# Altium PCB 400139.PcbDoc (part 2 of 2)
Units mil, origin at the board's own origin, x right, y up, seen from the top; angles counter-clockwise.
Board outline 2800 x 2160 mil, 2 copper layers (Top Layer, Bottom Layer), stack 61.8 mil thick; 154 components, 167 nets, 587 pads, 544 vias.
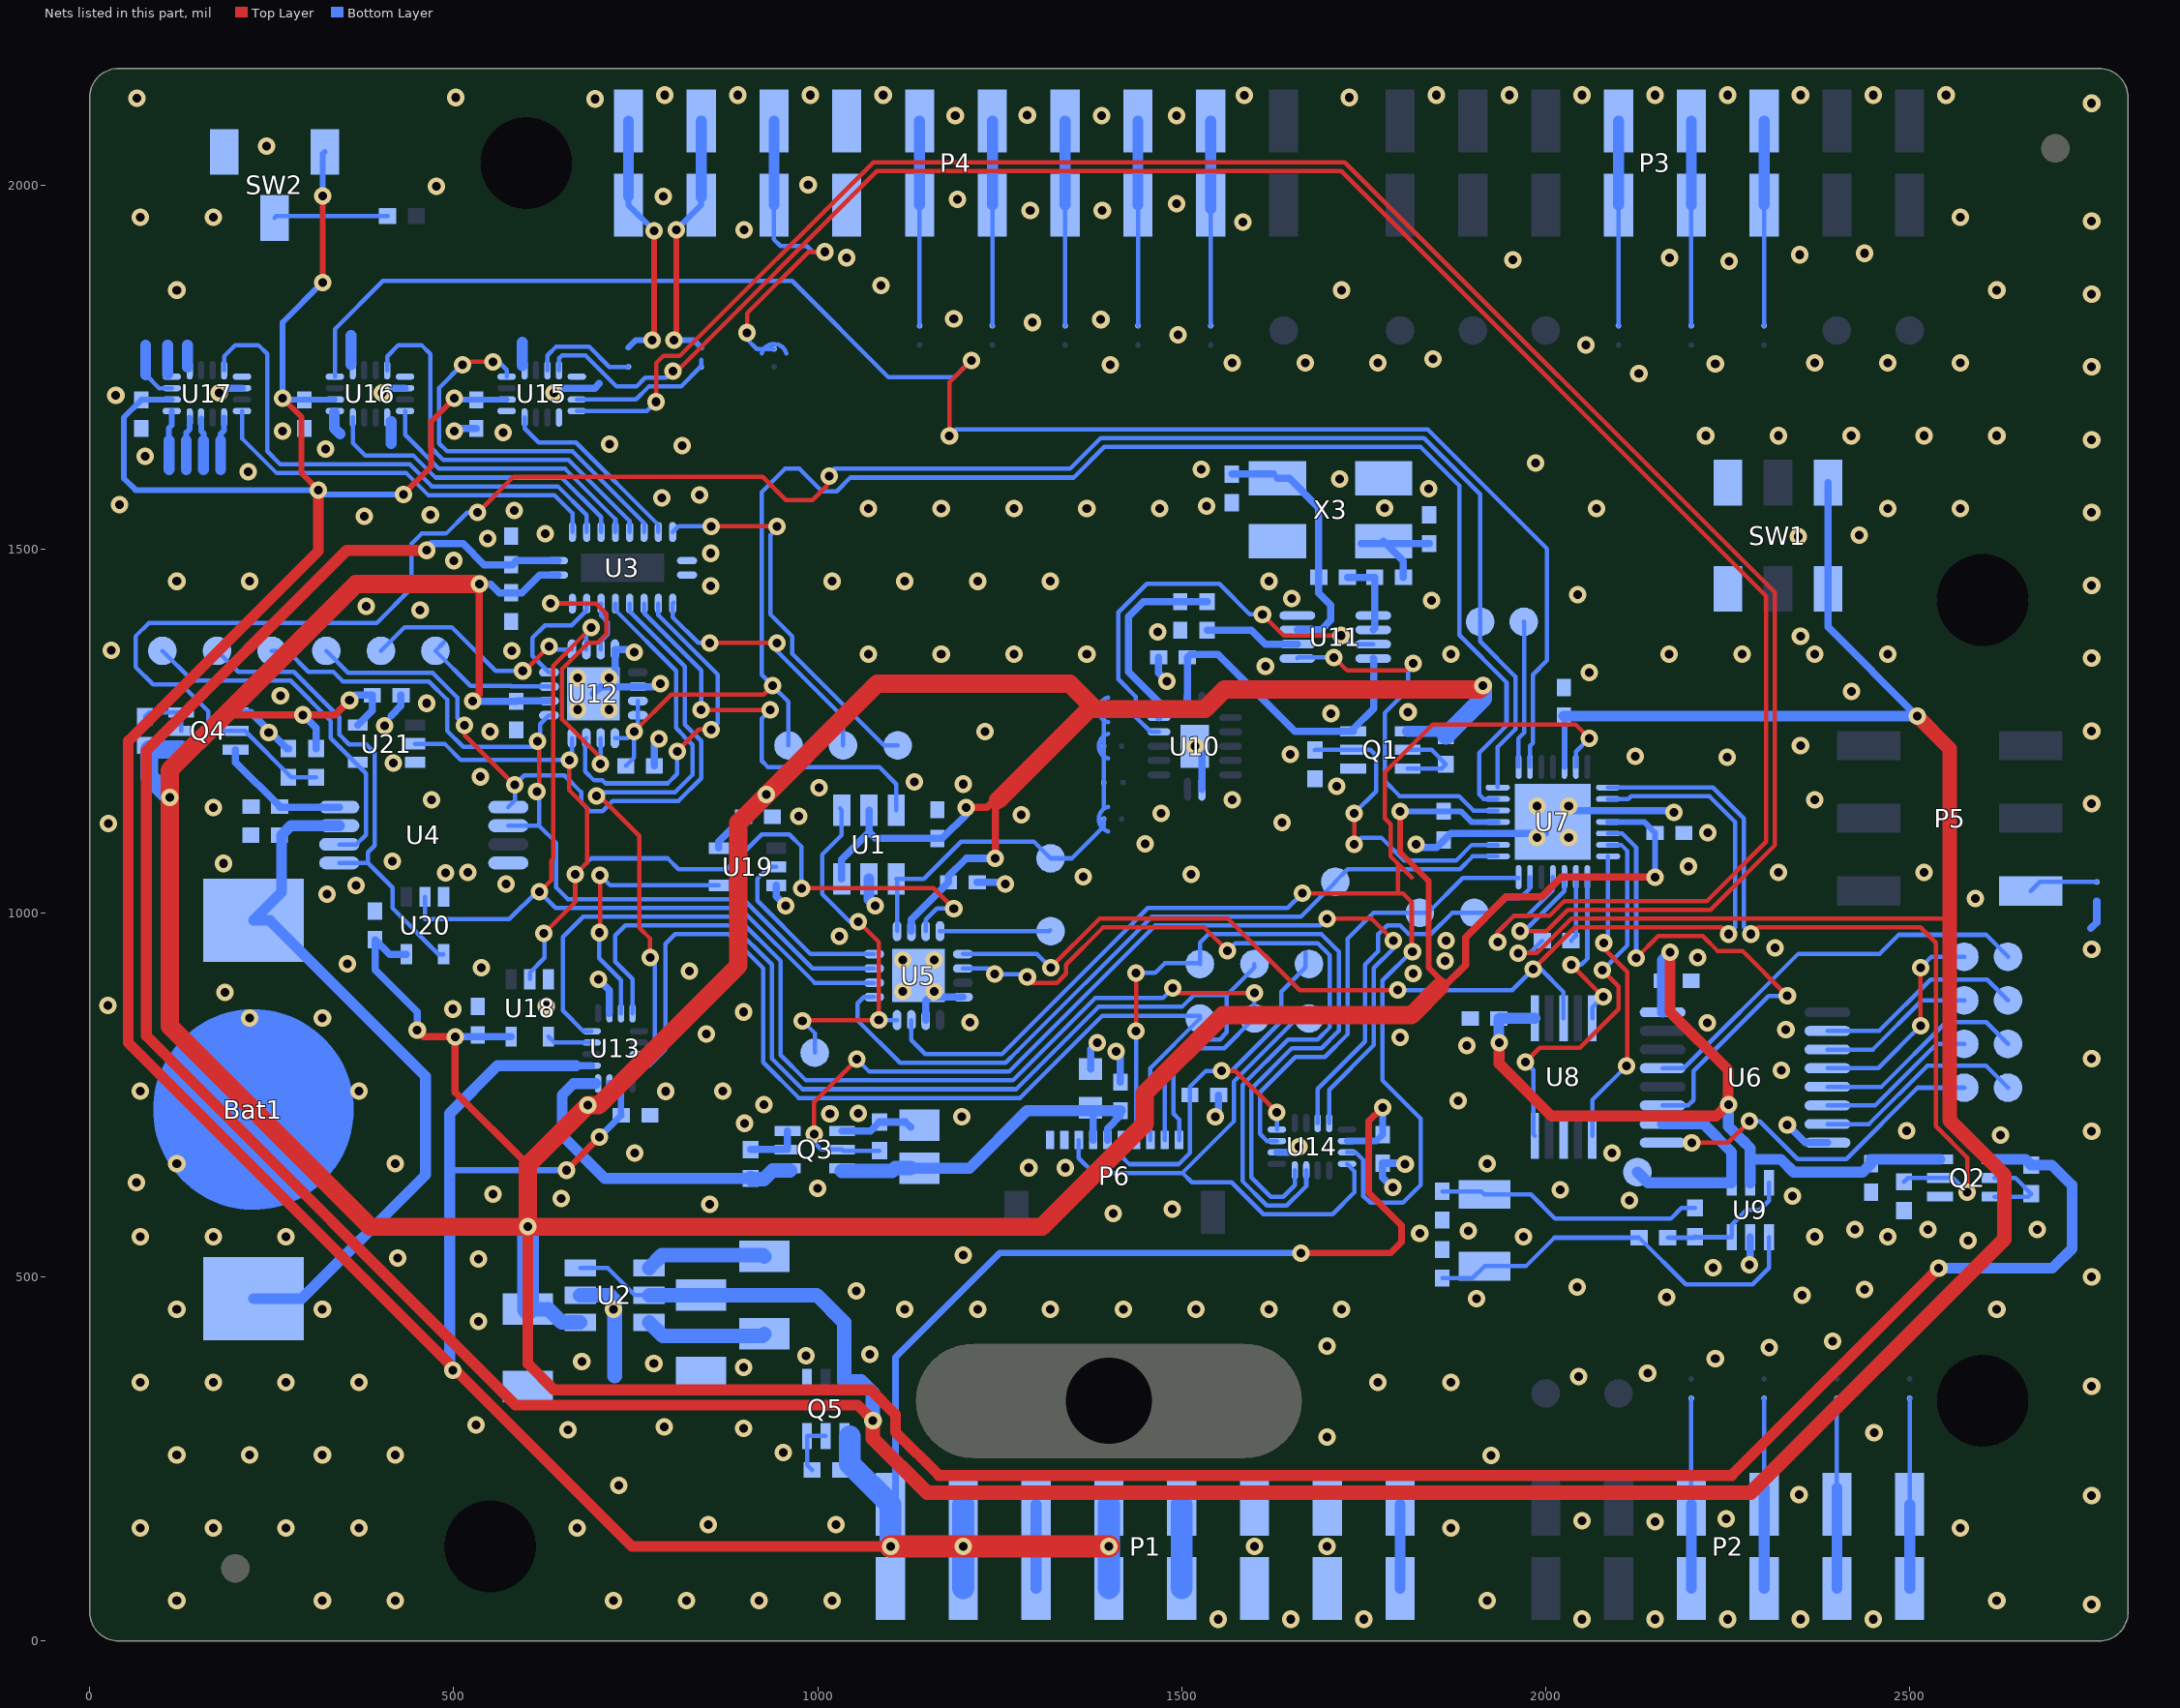
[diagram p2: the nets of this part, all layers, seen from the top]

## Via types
v1: diameter 24, hole 12, Top Layer to Bottom Layer, tented both sides, 544 vias

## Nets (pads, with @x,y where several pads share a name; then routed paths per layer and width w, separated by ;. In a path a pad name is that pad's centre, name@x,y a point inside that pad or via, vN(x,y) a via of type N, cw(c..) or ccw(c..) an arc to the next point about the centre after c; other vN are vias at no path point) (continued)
GND: Bat1.2 C1.1 C2.1 C4.1 C5.1 C6.1 C7.1 C8.1 C9.1 C10.1 C11.1 C12.1 C13.1 C14.1 C15.1 C16.1 C17.1 C18.1 C19.1 C20.2 C21.2 C22.1 C23.1 C24.2 C25.2 C26.1 C27.2 C28.1 C29.1 C30.1 C31.1 C32.1 C33.2 C34.2 C35.2 P1.6 P1.7 P4.7 P6.9 P6.10 Q1.1 Q2.1 Q3.1 Q4.1 Q5.1 R2.2 R4.2 R7.2 R8.1 R13.1 R14.2 SB13.1 SW1.3 SW1.6 SW2.3 U1.2 U2.2 U3.10 U3.11 U4.4 U5.4 U5.6 U5.17 U6.8 U7.3 U7.17 U7.29 U8.3 U9.2 U10.7 U10.15 U11.4 U12.4 U12.6 U12.17 U13.6 U14.6 U15.6 U16.6 U17.6 U18.3 U19.3 U20.3 U21.3 X3.2 X3.4 | length 1783.5
  Bottom Layer w10: v1(178,1714) 184.87,1720.87 U17.6@209.23,1720.87 ; Q4.1@200.4,1275.59 221.41,1275.59 271.31,1225.69 R14.2@273,1225.69 ; v1(402,1714) 408.87,1720.87 U16.6@433.23,1720.87 ; 414,1271 427.69,1284.69 C35.2@427.69,1299 ; v1(501,1662) 504.31,1665.32 C30.1@531,1665.32 ; v1(638,1714) 644.87,1720.87 U15.6@669.23,1720.87 693.87,1720.87 700,1727 ; U12.17@692,1301 701.84,1310.84 U12.6@753.02,1310.84 779.84,1310.84 v1(784,1315) ; v1(699,909) 714.13,893.87 U13.6@714.13,862.23 ; U12.17@721.53,1327 U12.4@721.53,1362.02 743.98,1362.02 v1(748,1358) ; R13.1@775.69,1202 775.69,1232.68 v1(782,1239) ; U19.3@943,1037.82 943,1023 v1(956,1010) ; Q3.1@1033.52,700.59 1072.65,700.59 R7.2@1084.87,712.81 1120.76,712.81 C16.1@1127.87,705.7 ; U5.6@1148.37,852.95 1148.37,879.37 1159,890 1164.55,884.45 U5.4@1199.55,884.45 ; C7.1@1219.21,1041.98 1256.02,1041.98 v1(1258,1040) ; C19.1@1374.87,785.67 1374.87,812.87 v1(1384,822) ; v1(1410,810) 1415.87,804.13 C18.1@1415.87,767.78 ; C22.1@1468.31,1351 1468.31,1329.68 v1(1480,1318) ; v1(1518,1229) 1527.84,1219.16 U10.7@1527.84,1169.94 ; v1(1546,720) 1550.69,724.68 C17.1@1550.69,750 ; U14.6@1630.77,671.13 1631.19,671.54 1653.54,671.54 v1(1661,679) ; v1(1790,623) 1776,637 C28.1@1776,656.31 1805.69,656.31 v1(1807,655) ; v1@1820,1090 1850,1090 1869.25,1109.25 U7.3@1934.21,1109.25 1999.25,1109.25 U7.29@2000,1110 ; U7.29@2030,1140 2030.75,1140.75 U7.17@2085.79,1140.75 2169.25,1140.75 v1@2170,1140 ; v1(2280,517.06) 2281,518.06 U9.2@2281,554.66 ; v1(2332,709) 2356.52,684.48 U6.8@2387.13,684.48 ; 2749,979 2757,987 SB13.1@2757,1016
  Bottom Layer w15: v1@1070.53,1018.47 U1.2@1070.53,1046.73
  Bottom Layer w20: U2.2@673.91,475 714.16,475 721.16,468 721.16,364.16
  other v1: 1550,30 1650,30 1750,30 2050,30 2150,30 2250,30 2350,30 2450,30 2750,50 119.75,55.47 319.75,55.47 419.75,55.47 719.75,55.47 819.75,55.47 919.75,55.47 1019.75,55.47 1919.75,55.47 2619.75,55.47 1600,130 1700,130 69.75,155.47 169.75,155.47 269.75,155.47 369.75,155.47 669.75,155.47 1869.75,155.47 2569.75,155.47 850,160 1025,160 2150,164 2050,165 2248,168 2750,200 2348,201 727,214 119.75,255.47 219.75,255.47 319.75,255.47 419.75,255.47 1925,255 953,259 1700,280 2451,286 657,290 898,292 789,294 531,297 2750,350 69.75,355.47 169.75,355.47 269.75,355.47 369.75,355.47 1769.75,355.47 1869.75,355.47 2045,363 2140,368 898,376 775,381 676,384 2233,388 984,392 1072,394 2307,403 1700,405 2394,412 534,439 119.75,455.47 319.75,455.47 719.75,455.47 1119.75,455.47 1219.75,455.47 1319.75,455.47 1419.75,455.47 1519.75,455.47 1619.75,455.47 1719.75,455.47 2619.75,455.47 1905,470 2166,472 2352,475 1053,481 2438,483 2043,486 2750,500 2230,513.06 534,525 423,526 1200,530 2580,550 69.75,555.47 169.75,555.47 269.75,555.47 1969.75,555.47 2369.75,555.47 2469.75,555.47 1827,560 1894,563.06 2425,565 2525,565 2675,565 1406,587 1487,593 852,600 2115,605 648,608 2339,611 554,614 2020,620 1000,622 64,630 1290,650 1340,650 119.75,655.47 419.75,655.47 1919.75,655.47 749,670 2091,670 2625,695 2750,700 2496,701 899.87,711.13 1198,720 1016.87,724.13 1056,725 926,737 1880,742 69.75,755.47 369.75,755.47 791,755 869.75,755.47 2323.95,784.05 2750,800 1892,818 1800,829 847,834 2330,840 2221.95,849.05 1209,850 219.75,855.47 319.75,855.47 898,864 499,868 627,872 25,873 186,891 1116.87,892.32 1160.18,892.32 1818,917 824,920 538,925 354,930 1862,934 1116.87,935.63 1160.18,935.63 2208.95,939.05 2750,950 2315,952 1863,962 1030,968 1079,1010 2590,1020 326,1026 366,1038 572,1040 1365,1050 1513,1053 489,1055 519.75,1055.47 2319.75,1055.47 2519.75,1055.47 2196,1064 184,1068 416,1071 1822,1094 1450,1095 1988.35,1103.35 2031.65,1103.35 2223,1110 26,1123 1638,1124 974,1133 1280,1135 1472,1137 2176,1138 170,1145 1988.35,1146.65 2031.65,1146.65 2750,1150 469.75,1155.47 1569.75,1155.47 2369.75,1155.47 1002,1172 1713,1174 1200,1177 1133,1180 537,1187 417,1206 2249,1214 2123,1215 1649,1218 2350,1230 246,1248 550,1249 1230,1249 2750,1250 405,1257 1705,1274 1811,1276 670.35,1279.35 713.65,1279.35 463,1288 262,1298 2420,1304 670.35,1322.65 713.65,1322.65 2060,1330 1615,1339 2750,1350 1069.75,1355.47 1169.75,1355.47 1269.75,1355.47 1369.75,1355.47 1869.75,1355.47 2169.75,1355.47 2269.75,1355.47 2369.75,1355.47 2469.75,1355.47 580,1360 30,1361 2350,1380 1467,1386 454,1416 380,1421 1843,1429 1651,1432 2044,1437 853,1449 2750,1450 119.75,1455.47 219.75,1455.47 1019.75,1455.47 1119.75,1455.47 1219.75,1455.47 1319.75,1455.47 1619.75,1455.47 500,1484 853,1494 547,1514 2347,1517 2431,1519 626,1521 377,1545 468,1547 2750,1550 583,1553 1069.75,1555.47 1169.75,1555.47 1269.75,1555.47 1369.75,1555.47 1469.75,1555.47 2069.75,1555.47 2469.75,1555.47 2569.75,1555.47 1779,1556 1534,1559 41,1561 786,1570 838,1574 1839,1583 1717,1596 218,1606 1527,1609 1986,1618 76,1627 324,1637 814,1642 714,1644 2750,1650 2219.75,1655.47 2319.75,1655.47 2419.75,1655.47 2519.75,1655.47 2619.75,1655.47 568,1660 265,1662 36,1711 2128,1741 2750,1750 1402,1753 2233,1754 1569.75,1755.47 1669.75,1755.47 1769.75,1755.47 2369.75,1755.47 2469.75,1755.47 2569.75,1755.47 1845,1761 2055,1780 1495,1794 1295,1811 1389,1815 1187,1816 2750,1850 119.75,1855.47 1719.75,1855.47 2619.75,1855.47 1087,1862 2252,1895 1955,1897 1040,1900 2170,1900 2349,1904 2438,1906 899,1938 1584,1949 2750,1950 69.75,1955.47 169.75,1955.47 2569.75,1955.47 1292,1965 1391,1965 1493,1974 1192,1980 788,1984 476,1998 987,2000 243,2053 1189,2095 1390,2095 1493,2095 1288,2096 2750,2112 694,2118 65,2119 503,2120 1730,2120 790,2123.31 890,2123.31 990,2123.31 1090,2123.31 1586,2123 1850,2123.31 1950,2123.31 2050,2123.31 2150,2123.31 2250,2123.31 2350,2123.31 2450,2123.31 2550,2123.31
HF_CLK_CTRL: TP30.1 U1.4 U5.8 | length 524.5
  Top Layer w6: v1(979,852) 979,853 v1(1084,853) 1084,960 v1(1056,988)
  Bottom Layer w6: v1(979,852) 996,835 TP30.1@996,808 ; U1.4@1030.53,1143.82 U1.4@1033.13,1141.22 1033.13,1107.13 1006,1080 1006,1026 1044,988 v1(1056,988) ; v1(1084,853) 1084.05,852.95 U5.8@1109,852.95
HF_OSC_CTRL: U3.7 U15.16 | length 536.8
  Top Layer w6: v1(512,1753) 516,1757 v1(554,1757)
  Bottom Layer w6: v1(512,1753) 480,1721 480,1645 491,1634 663.03,1634 761.53,1535.5 U3.7@761.53,1523.21 ; v1(554,1757) 561.77,1757 572.77,1746 U15.16@572.77,1736.62
HF_OSC_CTRL_3V3: U1.6 U3.14 | length 582.5
  Top Layer w6: v1(840,1279) v1(935,1279)
  Bottom Layer w6: U3.14@761.53,1424.79 761.53,1411.47 840,1333 v1(840,1279) ; v1(935,1279) 923,1267 923,1209 931.5,1200.5 1084.5,1200.5 1107.93,1177.07 U1.6@1107.93,1141.22 U1.6@1108.19,1141.22
HF_OSC_OUT: SB9.1 SB10.1 SB11.1 SB12.1 TP18.1 U1.1 U5.13 | length 549.2
  Bottom Layer w6: U5.13@1109,975 1109,1045.66 U1.1@1107.93,1046.73 1145.73,1046.73 1197,1098 1297,1098 TP18.1@1320,1075 1349,1075 1390.94,1116.94 1393,1119 SB12.1@1393,1129 ; 1393,1142.9 SB11.1@1393,1179 SB10.1@1393,1229 1393,1273 1395,1275
HF_OSC_OUT_SENSE: U3.8 U15.12 | length 263.3
  Bottom Layer w6: U15.12@597.38,1680.52 597.38,1665.62 617,1646 668,1646 781.21,1532.79 U3.8@781.21,1523.21
HF_OSC_OUT_SENSE_3V3: U3.13 U12.11 | length 485.4
  Top Layer w6: v1(807,1222) 837,1252 v1(854,1252)
  Bottom Layer w6: U12.11@682.16,1239.98 680.84,1238.66 680.84,1194.16 693,1182 704.7,1182 708.7,1178 794,1178 807,1191 v1(807,1222) ; U3.13@781.21,1424.79 781.21,1408.76 863,1326.97 863,1261 v1(854,1252)
HF_OSC_PWR_CTRL_3V3: Q1.2 R2.1 U7.2 | length 444.4
  Top Layer w6: v1(1737,1094) v1(1737,1137)
  Bottom Layer w6: R2.1@1683,1223.68 1683.31,1224 Q1.2@1735.6,1224 1759,1224 1767,1216 1767,1167 v1(1737,1137) ; v1(1737,1094) 1746,1103 1774.7,1103 1805.56,1072.13 1877.13,1072.13 1898.5,1093.5 U7.2@1934.21,1093.5
HF_OSC_S\T\_3V3: U7.5 U11.1 | length 521.4
  Top Layer w6: v1(1709,1351) 1727,1333 1808,1333 v1(1818,1343)
  Bottom Layer w6: U11.1@1658.83,1349.47 1660.36,1351 v1(1709,1351) ; v1(1818,1343) 1811,1336 1811,1307 1779,1275 1779,1181 1799.31,1160.69 1880.7,1160.69 1900.64,1140.75 U7.5@1934.21,1140.75
INT: U7.9 U16.16 | length 2349.1
  Top Layer w6: v1(1181,1655) 1181,1729 v1(1211,1759)
  Bottom Layer w6: U16.16@336.77,1736.62 336.77,1801.77 403,1868 965.03,1868 1097.03,1736 1188,1736 v1(1211,1759) ; v1(1181,1655) 1190,1664 1838,1664 2002.01,1499.99 2002.01,1346.99 1982.25,1327.22 1982.25,1233.25 1978.5,1229.5 U7.9@1978.5,1200.79
LCD_CS: U3.5 U16.8 | length 387.2
  Bottom Layer w6: U16.8@433.23,1689.38 433.23,1656.77 480,1610 653.09,1610 722.16,1540.93 U3.5@722.16,1523.21
LCD_CS_3V3: U3.16 U13.11 | length 826.7
  Top Layer w6: v1(696,1161) 699.7,1161 755,1105.7 755,979.7 770,964.7 v1(770,939)
  Bottom Layer w6: v1@696,1166 804.09,1166 828,1189.91 828,1230.7 817.17,1241.53 817.17,1242.17 805.45,1253.89 805.45,1332.55 722.16,1415.84 U3.16@722.16,1424.79 ; U13.11@754.48,806.13 766.05,806.13 776.28,816.35 776.28,932.72 v1(770,939)
LCD_DISP_3V3: TP38.1 U7.28 U14.7 | length 638.5
  Bottom Layer w6: U14.7@1630.77,686.87 1617.13,686.87 1607.5,696.5 1607.5,753.58 1656.23,802.31 1696.82,802.31 1727.69,833.18 1727.69,964.38 1763.3,1000 TP38.1@1827,1000 1838,1000 1886.13,1048.13 U7.28@1962.76,1048.13
LCD_EXTCOMIN_3V3: U5.2 U14.3 | length 1093.7
  Top Layer w6: v1(1288,912) 1296,904 1328.7,904 1341,916.3 1341,929.03 1391.97,980 1531,980 v1(1563,948)
  Bottom Layer w6: U5.2@1199.55,923.82 1235.18,923.82 v1(1243,916) 1284,916 v1(1288,912) ; v1(1563,948) 1573.69,958.69 1686.88,958.69 1703.69,941.88 1703.69,843.12 1686.88,826.31 1646.29,826.31 1583.5,763.53 1583.5,631.84 1617.1,598.23 1644.44,598.23 1671.13,624.91 U14.3@1671.13,646.52
LCD_EXTMODE_3V3: U5.7 U7.13 U14.15 | length 1976.6
  Top Layer w6: v1(1666,1027) 1797,1027 ; 1797,1066 1797,1027 ; v1@1816,947 1816,1015 1804,1027 1797,1027 ; 1816,1048.75 1787,1077.75 1787,1122 1779.31,1129.69 1779.31,1193.34 1844.97,1259 2041,1259 v1(2060,1240)
  Bottom Layer w6: U5.7@1128.69,852.95 1128.69,825.31 1148,806 1253.03,806 1422.03,975 1453.71,1006.69 1645.69,1006.69 v1(1666,1027) ; U14.15@1727.23,671.13 1738.87,671.13 1749.02,660.98 1749.02,611.02 1749.98,611.02 1759,602 1804,602 1828,626 1828,718 1776,770 1776,907 v1@1816,947 ; U7.13@2041.5,1200.79 2041.5,1221.5 v1(2060,1240)
  other v1: 1817,947
LCD_PWR_CTRL: Q3.2 R7.1 U14.12 | length 1363.7
  Top Layer w6: v1(995,696) 995,740 v1(1054,799) ; v1(1700,992) 1761,992 v1(1791,962)
  Bottom Layer w6: v1(995,696) 995,685 1005,675 Q3.2@1033.53,675 1035.08,673.44 R7.1@1084.87,673.44 ; v1(1054,799) 1071,782 1262.97,782 1463.66,982.69 1690.69,982.69 v1(1700,992) ; U14.12@1702.62,711.48 1702.62,757.2 1764,818.58 1764,924.33 1791,951.33 v1(1791,962)
LCD_PWR_CTRL_3V3: TP37.1 U7.27 U14.11 | length 553.6
  Bottom Layer w6: U14.11@1686.87,711.48 1686.87,758.43 1752,823.55 1752,929.3 1770,947.3 1770,970.7 1782.3,983 1800,983 1812,971 1842.3,971 1871.3,1000 TP37.1@1902,1000 1926,1000 1946,1020 1964.63,1020 1978.5,1033.87 U7.27@1978.5,1049.21
LCD_SI_LOCAL: U13.7 U19.4 | length 371.7
  Top Layer w6: v1(700,973) 701,974 v1(701,1052)
  Bottom Layer w6: v1(700,973) 700,937.7 729.87,907.82 U13.7@729.87,862.23 ; v1(701,1052) 715.18,1037.82 U19.4@864.26,1037.82
LCD_SPI_DATA_CTRL_3V3: TP8.1 U5.9 U7.1 | length 1071.1
  Bottom Layer w6: U5.9@1077.5,884.45 1063.45,884.45 1054.87,875.87 1054.87,852.44 1113.3,794 1258,794 1274.5,810.5 1458.69,994.69 1663.38,994.69 1711,1042.3 TP8.1@1711,1043 1728.13,1060.13 1882.1,1060.13 1899.73,1077.76 U7.1@1934.21,1077.76
LF_CNT_3V3: U5.1 U7.16 U8.8 | length 1605.8
  Top Layer w6: v1(1320,925) 1387,992 1564,992 1662,894 v1(1797,894) ; v1(1983,923) 2040.31,980.31 2241.69,980.31 v1(2251,971)
  Bottom Layer w6: U5.1@1199.55,943.5 1301.5,943.5 v1(1320,925) ; v1(1797,894) 1954,894 v1(1983,923) 1993,923 2024.57,891.43 U8.8@2024.57,855.47 ; U7.16@2085.79,1156.5 2113.5,1156.5 2117.24,1160.24 2224.76,1160.24 2260,1125 2260,980 v1(2251,971)
LF_CNTR_CLR_3V3: U6.11 U7.19 | length 709.7
  Top Layer w6: v1(2124.36,938) 2154.68,968.31 2215.69,968.31 2236,948 2270,948 v1(2332,886)
  Bottom Layer w6: U7.19@2085.79,1109.25 2105.08,1109.25 2124.36,1089.97 v1(2124.36,938) ; U6.11@2160.76,735.66 2195.56,735.66 2203,743.1 2203,783.03 2305.97,886 v1(2332,886)
LF_OSC_OUT: TP19.1 U6.10 U9.4 | length 288.2
  Bottom Layer w15: TP19.1@2126,644.06 2140.6,629.46 U9.4@2255.41,629.46 2255.41,671.66 2217,710.07 U6.10@2160.76,710.07
LF_OSC_PWR_CTRL_3V3: Q2.2 R4.1 U7.15 | length 1091.4
  Top Layer w6: v1(2282,971) 2291.31,980.31 2514.69,980.31 2536,959 2536,707.13 2579,664.13 v1(2579,616.31)
  Bottom Layer w6: U7.15@2085.79,1172.24 2229.73,1172.24 2272,1129.97 2272,981 v1(2282,971) ; R4.1@2492,630.68 2497.32,636 Q2.2@2541.6,636 2559.31,636 v1(2579,616.31)
LF_SEL0_3V3: U7.21 U8.1 | length 419.3
  Top Layer w6: v1(2080,959) 2080,951 2112,919 2112,791 v1(2111,790)
  Bottom Layer w6: U8.1@2063.95,694.05 2063.95,742.95 v1(2111,790) ; v1(2080,959) 2085.79,964.79 U7.21@2085.79,1077.76
LF_SEL1_3V3: U7.22 U8.10 | length 235.6
  Top Layer w6: v1(2035,929) v1(2079,885)
  Bottom Layer w6: v1(2035,929) 2049,929 2057.24,937.24 U7.22@2057.24,1049.21 ; U8.10@2063.94,855.47 2063.94,869.94 v1(2079,885)
LF_SEL_EN_3V3: U7.20 U8.5 | length 535.1
  Top Layer w6: v1(1972,795) 1992,815 2047,815 2100,868 2100,899.34 v1(2078,921.34)
  Bottom Layer w6: v1(1972,795) 1982.95,784.05 1982.95,696.31 U8.5@1985.2,694.05 ; v1(2078,921.34) 2112.36,955.7 2112.36,1085 2103.86,1093.5 U7.20@2085.79,1093.5
MISO: U3.3 U17.4 | length 721.9
  Bottom Layer w6: U17.4@184.62,1745.48 184.62,1764.62 200,1780 231.7,1780 244,1767.7 244,1634 262,1616 440,1616 470,1586 643.15,1586 682.79,1546.36 U3.3@682.79,1523.21
MISO_3V3: U3.18 U12.16 | length 155.9
  Bottom Layer w6: U12.16@630.98,1330.53 608.34,1353.17 608.34,1378 625.34,1395 662,1395 682.79,1415.79 U3.18@682.79,1424.79
MISO_LOCAL: TP27.1 U4.2 U5.11 U12.13 | length 1212.1
  Top Layer w6: v1(615,1236) 617.2,1233.8 v1@617.2,1166.8
  Bottom Layer w6: TP27.1@250,1360 272,1360 300.69,1331.31 334.69,1331.31 348,1318 466.03,1318 491,1293.03 491,1250 513,1228 v1@613,1228 ; U4.2@575.14,1119.8 617,1119.8 617.2,1120 ; v1@617.2,1166.8 617.2,1120 ; v1@618.75,1243.75 618.75,1259.25 U12.13@630.98,1271.47 ; U5.11@1077.5,923.82 993.15,923.82 897.97,1019 657,1019 641,1035 641,1096.2 617.2,1120
  other v1: 614.2,1166.8
MLCD_DISP: C17.2 P6.5 TP24.1 U14.8 | length 611.9
  Top Layer w6: v1(1555,783) 1574,783 v1(1630.77,726.23)
  Bottom Layer w6: P6.5@1417.72,688.09 1417.72,665.28 1428,655 1496,655 1511.36,670.36 C17.2@1511.31,750 C17.2@1511.31,750 1511.31,761.31 1533,783 v1(1555,783) 1568.57,783 1637,851.43 1637,892 1670,925 TP24.1@1670,945.7 ; U14.8@1630.77,702.62 v1(1630.77,726.23)
MLCD_EXTCOMIN: P6.4 TP23.1 U14.4 | length 1038.9
  Top Layer w6: v1(1437.4,838) v1(1437.4,917.6)
  Bottom Layer w6: P6.4@1437.4,688.09 v1(1437.4,838) ; v1(1437.4,917.6) 1463.6,917.6 1477,931 1524,931 TP23.1@1525,930 1525,959 1536.69,970.69 1691.85,970.69 1715.69,946.85 1715.69,838.15 1691.85,814.31 1651.26,814.31 1595.5,758.55 1595.5,636.81 1622.07,610.23 1639.47,610.23 1655.38,626.14 U14.4@1655.38,646.52
MLCD_EXTMODE: P6.8 TP25.1 U14.16 | length 784.9
  Bottom Layer w6: P6.8@1358.66,688.09 1358.66,663.34 1379,643 1501,643 ; TP25.1@1675,855 1658,855 1571.5,768.5 1571.5,713.5 1501,643 ; U14.16@1727.23,655.38 1737.02,645.58 1737.02,616 1707.25,586.23 1612.13,586.23 1568.36,630 1514,630 1501,643
MLCD_SCLK: P6.1 TP20.1 U13.4 | length 1613.4
  Top Layer w6: v1(1488,897) 1495,890 v1(1600,890)
  Bottom Layer w6: U13.4@689.52,837.62 678.38,837.62 650,866 650,967 678,995 888.03,995 949,934.03 949,804.94 983.94,770 1267.94,770 1380.94,883 1474,883 v1(1488,897) ; P6.1@1496.46,688.09 1496.46,716.54 1488.77,724.23 1488.77,784.83 1518.26,814.31 1558.31,814.31 1599,855 TP20.1@1600,855 v1(1600,890)
MLCD_SCS: P6.3 TP22.1 U13.12 | length 1344.8
  Bottom Layer w6: U13.12@754.48,790.38 768.38,790.38 791,813 791,957.7 804.3,971 878.09,971 925,924.09 925,795 974,746 1277.88,746 1390.88,859 1525,859 TP22.1@1525,855 1457.09,787.09 P6.3@1457.09,688.09
MLCD_SI: P6.2 TP21.1 U13.8 | length 1500.4
  Bottom Layer w6: U13.8@745.62,862.23 745.62,909.38 722,933 722,969 736,983 883.06,983 937,929.06 937,799.97 978.97,758 1272.91,758 1385.91,871 1500.43,871 1516.43,887 1562,887 ; P6.2@1476.77,688.09 1476.77,789.8 1513.29,826.31 1552.31,826.31 1562,836 1562,887 ; TP21.1@1600,930 1600,925 1562,887
MOSI: U3.4 U16.12 | length 438.7
  Bottom Layer w6: U16.12@361.38,1680.52 361.38,1645.62 379,1628 445.03,1628 475.03,1598 648.12,1598 702.47,1543.65 U3.4@702.47,1523.21
MOSI_3V3: U3.17 U12.3 | length 70.9
  Bottom Layer w6: U12.3@701.84,1362.02 701.84,1372.84 712,1383 712,1399 702.47,1408.53 U3.17@702.47,1424.79
MOSI_LOCAL: U5.10 U12.2 U20.2 | length 1140
  Top Layer w6: v1(618,1029) 634,1045 634,1071.97 637,1074.97 637,1340 v1(689,1392)
  Bottom Layer w6: U20.2@460.59,1022 460.59,991.41 576.41,991.41 614,1029 v1(618,1029) 640,1007 893,1007 995.87,904.13 U5.10@1077.5,904.13 ; U12.2@682.16,1362.02 682.16,1385.16 v1(689,1392)
NetC3_1: C3.1 U2.4 | length 166.7
  Bottom Layer w20: U2.4@768.4,512.4 786,530 925.15,530 C3.1@927,528.15
NetC3_2: C3.2 U2.6 | length 167.6
  Bottom Layer w20: U2.6@768.4,437.6 787.1,418.9 924.05,418.9 C3.2@927,421.85
NetC11_2: C11.2 R19.2 U10.13 | length 272.5
  Bottom Layer w10: U10.13@1468.79,1268.37 1468.79,1289.21 1427,1331 1427,1407 1447.69,1427.69 C11.2@1498,1427.69 R19.2@1535,1427.69
NetC20_1: C20.1 R9.1 U9.1 X2.2 | length 549.6
  Bottom Layer w6: C20.1@1858,498.38 1899.53,498.38 X2.2@1916,514.85 1972.85,514.85 2012,554 R9.1@2128.31,554 2192.31,490 2284,490 2306.59,512.59 U9.1@2306.59,554.66
NetC21_1: C21.1 R10.1 X2.1 | length 368.7
  Bottom Layer w6: C21.1@1858,617.75 1911.53,617.75 X2.1@1916,613.28 1979.72,613.28 2013,580 2171.72,580 2186.47,594.75 R10.1@2205,594.75
NetC24_1: C24.1 R11.1 U11.3 X3.1 | length 343.6
  Bottom Layer w10: C24.1@1569,1602.68 X3.1@1626.01,1602.68 ; X3.1@1631.64,1597.06 1647.94,1597.06 1688.31,1556.68 R11.1@1688.31,1461 1688.31,1439.68 1705,1423 1705,1402 1691.84,1388.84 U11.3@1658.83,1388.84
NetC25_1: C25.1 R12.1 X3.3 | length 154.1
  Bottom Layer w10: X3.3@1746.69,1507.32 X3.3@1780.43,1507.32 ; X3.3@1777.31,1510.44 X3.3@1780.43,1507.32 ; R12.1@1804.69,1461 1804.69,1483.06 X3.3@1780.43,1507.32 ; C25.1@1840,1507.32 X3.3@1780.43,1507.32
NetP2_3: P2.3 SB14.2 | length 283.8
  Bottom Layer w6: P2.3@2200,210.4 P2.3@2200,187.68 SB14.2@2200,333.4
  Bottom Layer w15: P2.3@2200,72.32 P2.3@2200,187.68
NetP2_4: P2.4 SB15.2 | length 283.4
  Bottom Layer w6: P2.4@2300,187.68 SB15.2@2300,333.4
  Bottom Layer w15: P2.4@2300,72.32 2300,130 P2.4@2300,210
NetP2_5: P2.5 SB16.2 | length 283.4
  Bottom Layer w6: P2.5@2400,187.68 SB16.2@2400,333.4
  Bottom Layer w15: P2.5@2400,72.32 2400,130 P2.5@2400,210
NetP2_6: P2.6 SB17.2 | length 261.1
  Bottom Layer w6: P2.6@2500,187.68 SB17.2@2500,333.4
  Bottom Layer w15: P2.6@2500,72.32 2500,130 P2.6@2500,187.68
NetP3_3: P3.3 SB26.2 | length 281.1
  Bottom Layer w6: SB26.2@2300,1806.6 P3.3@2300,1972.32
  Bottom Layer w15: P3.3@2300,1972.32 P3.3@2300,2087.68
NetP3_4: P3.4 SB18.2 | length 281.1
  Bottom Layer w6: SB18.2@2200,1806.6 P3.4@2200,1972.32
  Bottom Layer w15: P3.4@2200,1972.32 P3.4@2200,2087.68
NetP3_5: P3.5 SB20.2 | length 281.1
  Bottom Layer w6: SB20.2@2100,1806.6 P3.5@2100,1972.32
  Bottom Layer w15: P3.5@2100,1972.32 P3.5@2100,2087.68
NetP4_2: P4.2 SB7.2 | length 281.1
  Bottom Layer w6: SB7.2@1540,1806.6 P4.2@1540,1967
  Bottom Layer w15: P4.2@1540,1967 P4.2@1540,2087.68
NetP4_3: P4.3 SB25.2 | length 281.1
  Bottom Layer w6: SB25.2@1440,1806.6 P4.3@1440,1972.32
  Bottom Layer w15: P4.3@1440,1972.32 P4.3@1440,2087.68
NetP4_4: P4.4 SB24.2 | length 281.1
  Bottom Layer w6: SB24.2@1340,1806.6 P4.4@1340,1972.32
  Bottom Layer w15: P4.4@1340,1972.32 P4.4@1340,2087.68
NetP4_5: P4.5 SB23.2 | length 281.1
  Bottom Layer w6: SB23.2@1240,1806.6 P4.5@1240,1972.32
  Bottom Layer w15: P4.5@1240,1972.32 P4.5@1240,2087.68
NetP4_6: P4.6 SB22.2 | length 281.1
  Bottom Layer w6: SB22.2@1140,1806.6 P4.6@1140,1972.32
  Bottom Layer w15: P4.6@1140,1972.32 P4.6@1140,2087.68
NetP4_8: P4.8 SB6.2 | length 459.8
  Top Layer w6: v1(903,1797) 903,1823.56 987.44,1908 v1(1010,1908)
  Bottom Layer w6: v1(903,1797) 903,1788 916.4,1774.6 926.1,1774.6 SB6.2@940,1774.6 ; P4.8@940,1972.32 940,1925 949,1916 984.91,1916 992.91,1908 v1(1010,1908)
  Bottom Layer w15: P4.8@940,1972.32 P4.8@940,2087.68
NetP4_9: P4.9 SB27.2 | length 358.4
  Top Layer w8: v1(802.4,1786.6) 805.68,1789.88 v1(805.68,1938)
  Bottom Layer w8: v1(802.4,1786.6) 830,1786.6 SB27.2@840,1776.6 ; v1(805.68,1938) P4.9@840,1972.32 P4.9@840,1983
  Bottom Layer w15: P4.9@840,1983 P4.9@840,2087.68
NetP4_10: P4.10 SB28.2 | length 353.5
  Top Layer w8: v1(772.4,1786.6) 775.32,1789.52 v1(775.32,1937)
  Bottom Layer w8: SB28.2@740,1776.6 750,1786.6 v1(772.4,1786.6) ; P4.10@740,1984 740,1972.32 v1(775.32,1937)
  Bottom Layer w15: P4.10@740,1984 P4.10@740,2087.68
NetP5_6: P5.6 SB13.2 | length 96
  Bottom Layer w6: P5.6@2666.22,1030 2678.82,1042.6 SB13.2@2757,1042.6
NetQ1_5: Q1.5 Q1.6 R3.2 | length 115.8
  Bottom Layer w6: Q1.6@1810.4,1198.41 1857.09,1198.41 R3.2@1863,1204.31 1843.31,1224 Q1.5@1810.4,1224
NetQ2_5: Q2.5 Q2.6 R5.2 | length 111.8
  Bottom Layer w6: Q2.6@2616.4,610.41 2663.09,610.41 R5.2@2667,614.31 2645.31,636 Q2.5@2616.4,636
NetQ3_5: Q3.5 Q3.6 R6.2 | length 76.2
  Bottom Layer w10: R6.2@908.06,675 Q3.5@958.72,675 Q3.6@958.72,700.59
NetQ4_5: Q4.5 Q4.6 R15.2 | length 77.6
  Bottom Layer w6: R15.2@76,1269.69 81.91,1275.59 Q4.6@125.6,1275.59 Q4.5@125.6,1250
NetQ5_5: Q5.5 Q5.6 R17.2 | length 75
  Bottom Layer w6: R17.2@992.31,235 985.41,241.91 Q5.6@985.41,281.6 Q5.5@1011,281.6
NetR1_1: R1.1 U7.23 | length 90
  Bottom Layer w6: R1.1@2034.69,962 2041.5,968.81 U7.23@2041.5,1049.21
NetR9_2: R9.2 R10.2 U9.3 U9.6 | length 195.1
  Bottom Layer w6: R9.2@2167.69,554 2203.62,554 R10.2@2205,555.38 2205.72,554.66 U9.3@2255.41,554.66 2255.41,571.47 2276,592.06 2294,592.06 2306.59,604.65 U9.6@2306.59,629.46
NetR11_2: R11.2 R12.2 U11.5 U11.6 | length 110.7
  Bottom Layer w10: R11.2@1727.69,1461 R12.2@1765.31,1461 1765.31,1390.99 U11.6@1763.17,1388.84
NetR18_2: R18.2 SW2.2 | length 156.3
  Bottom Layer w6: SW2.2@254,1954.72 256.28,1957 R18.2@409.31,1957
NetR19_1: R19.1 U11.2 | length 131.8
  Bottom Layer w10: R19.1@1535,1388.32 1595.69,1388.32 1614.84,1369.16 U11.2@1658.83,1369.16
NetTP1_1: TP1.1 U5.16 | length 151.4
  Bottom Layer w6: U5.16@1168.06,975 1318,975 TP1.1@1319,976
NetTP2_1: TP2.1 U12.15 | length 193.2
  Bottom Layer w6: TP2.1@486.69,1371.69 TP2.1@475,1360 523.31,1311.69 578.81,1311.69 579,1311.5 630.98,1311.5 U12.15@630.98,1310.84
NetTP3_1: TP3.1 U12.1 | length 316.4
  Top Layer w6: v1(594.92,1332.5) 597.5,1332.5 v1(631,1366)
  Bottom Layer w6: TP3.1@400,1360 432.5,1392.5 497.5,1392.5 557.6,1332.4 594.83,1332.4 v1(594.92,1332.5) ; v1(631,1366) 634.98,1362.02 U12.1@662.47,1362.02
NetTP5_1: TP5.1 U7.8 | length 202.4
  Bottom Layer w6: U7.8@1962.76,1200.79 1962.76,1239.76 1970.25,1247.25 1970.25,1399.75 TP5.1@1970,1400
NetTP6_1: TP6.1 U3.9 | length 538.9
  Top Layer w6: v1(854,1531) v1@947,1531
  Bottom Layer w6: U3.9@800.9,1523.21 808.69,1531 v1(854,1531) ; v1@947,1531 935,1519 935,1410 965,1380 965,1356 1091,1230 TP6.1@1110,1230
  other v1: 944,1531
NetTP7_1: TP7.1 U3.12 | length 356.8
  Top Layer w6: v1(852,1371) v1(944,1371)
  Bottom Layer w6: U3.12@802.11,1426 U3.12@800.9,1424.79 800.9,1406.04 835.94,1371 v1(852,1371) ; v1(944,1371) 944,1360 1035,1269 TP7.1@1035,1230
NetTP10_1: TP10.1 U6.9 | length 448.9
  Top Layer w6: v1(2200.48,684.48) 2250.48,684.48 v1(2280,714)
  Bottom Layer w6: v1(2280,714) 2293.93,714 2345.93,662 2412.91,662 2510.91,760 TP10.1@2575,760
NetTP11_1: TP11.1 U6.7 | length 293.4
  Bottom Layer w6: U6.7@2387.13,710.07 2444.01,710.07 2523.94,790 2605,790 TP11.1@2635,760
NetTP12_1: TP12.1 U6.6 | length 222.8
  Bottom Layer w6: U6.6@2387.13,735.66 2452.63,735.66 2536.97,820 TP12.1@2575,820
NetTP13_1: TP13.1 U6.5 | length 297.1
  Bottom Layer w6: U6.5@2387.13,761.25 2461.25,761.25 2550,850 2605,850 TP13.1@2635,820
NetTP14_1: TP14.1 U6.3 | length 215.9
  Bottom Layer w6: U6.3@2387.13,812.43 2449.4,812.43 2516.97,880 TP14.1@2575,880
NetTP15_1: TP15.1 U6.2 | length 289
  Bottom Layer w6: U6.2@2387.13,838.02 2458.02,838.02 2528.69,908.69 2606.31,908.69 TP15.1@2635,880
NetTP16_1: TP16.1 U6.4 | length 298.2
  Top Layer w6: v1(2515,845) v1(2515,925)
  Bottom Layer w6: U6.4@2387.13,786.84 2456.84,786.84 v1(2515,845) ; v1(2515,925) 2530,940 TP16.1@2575,940
NetTP17_1: TP17.1 U6.13 | length 562.5
  Bottom Layer w6: U6.13@2160.76,786.84 2189.84,786.84 2347.05,944.05 2459.05,944.05 2485,970 2605,970 TP17.1@2635,940
NetTP26_1: TP26.1 U4.5 U20.4 | length 655.4
  Bottom Layer w6: TP26.1@175,1360 204,1331 280.67,1331 343,1268.67 343,1245.05 356.38,1231.67 380,1231.67 391.42,1220.25 391.42,1092.42 382.39,1083.39 382.39,1068.61 ; U4.5@342.86,1068.61 367.61,1068.61 382.39,1068.61 ; U20.4@486.18,943.26 479.36,943.26 416,1006.62 416,1035 382.39,1068.61
NetTP28_1: TP28.1 U4.6 U21.4 | length 489.3
  Bottom Layer w6: TP28.1@100,1360 141,1319 275.7,1319 331,1263.7 331,1240.08 364.26,1206.82 379.42,1191.66 379.42,1107.42 366.2,1094.2 U4.6@342.86,1094.2
NetU5_12: U5.12 U19.2 | length 253.8
  Bottom Layer w6: U19.2@943,1063.41 933.41,1063.41 917,1047 917,1016.94 990.44,943.5 U5.12@1077.5,943.5
NetU5_15: U5.15 U12.12 U18.2 U21.2 | length 1288.5
  Top Layer w6: v1(624,972) 667,1015 v1(667,1053) 683,1069 683,1144.3 659,1168.3 v1(659,1210) ; v1(978,1034) 1159,1034 v1(1187,1006)
  Bottom Layer w6: U21.2@447,1232.41 487.59,1232.41 510,1210 v1(659,1210) 662.47,1213.47 U12.12@662.47,1239.98 ; U18.2@604.59,909 604.59,917.89 625,938.3 625,971 v1(624,972) ; v1(667,1053) 689,1075 794,1075 809,1060 875,1060 923,1108 961,1108 978,1091 v1(978,1034) ; U5.15@1148.37,975 1148.37,990.71 1163.66,1006 v1(1187,1006)
NetU10_12: U10.12 U11.7 | length 594.7
  Top Layer w6: v1(1611,1410) 1640,1381 v1(1719,1381)
  Bottom Layer w6: U10.12@1468.79,1248.68 1457.31,1248.68 1437.05,1268.95 1437.05,1297 1413,1321.05 1413,1412.8 1452.2,1452 1551.8,1452 1593.8,1410 v1(1611,1410) ; v1(1719,1381) 1730.84,1369.16 U11.7@1763.17,1369.16
RAM_CS: U3.6 U16.4 | length 548.7
  Bottom Layer w6: U16.4@408.62,1745.48 408.62,1764.62 424,1780 455.7,1780 468,1767.7 468,1640.03 486.03,1622 658.06,1622 741.84,1538.22 U3.6@741.84,1523.21
RAM_CS_3V3: TP29.1 U3.15 U4.1 | length 982.7
  Top Layer w6: v1(515,1258) 515,1244 v1@583.5,1175.5
  Bottom Layer w6: TP29.1@325,1360 355,1330 471,1330 505.31,1295.69 505.31,1267.69 v1(515,1258) ; U4.1@575.14,1145.39 584,1154.24 v1(584,1176) 597,1189 652.06,1189 675,1166.06 675,1152.3 687.3,1140 704.7,1140 718.7,1154 809.06,1154 840,1184.94 840,1236.3 817.45,1258.86 817.45,1338.55 741.84,1414.16 U3.15@741.84,1424.79
RAM_PWR_CTRL_3V3: Q4.2 R14.1 R16.2 TP4.1 U7.7 | length 2859.6
  Top Layer w6: v1(533,1550) 582,1599 924.3,1599 956.3,1567 993,1567 1013,1587 v1@1013,1600
  Bottom Layer w6: R16.2@311,1186.31 277,1186.31 213.32,1250 Q4.2@200.4,1250 177,1250 163,1264 163,1277 126,1314 87,1314 63,1338 63,1380 81,1398 394,1398 442,1446 442,1507 456,1521 489.5,1521 518.5,1550 v1(533,1550) ; v1@533,1555 v1@538,1555 ; v1@1013,1600 1023,1610 1346.7,1610 1388.7,1652 1833.03,1652 1910,1575.03 TP4.1@1910,1400 1910,1373 1958.25,1324.75 1958.25,1252.22 1934.21,1228.18 U7.7@1934.21,1172.24
  other v1: 1016,1600
RST: P1.3 | length 115.4
  Bottom Layer w15: P1.3@1300,72.32 1300,130 P1.3@1300,187.68
SCK: U3.2 U17.8 | length 559.9
  Bottom Layer w6: U17.8@209.23,1689.38 209.23,1651.8 257.03,1604 435.03,1604 465.03,1574 638.18,1574 663.1,1549.07 U3.2@663.1,1523.21
SCK_3V3: U3.19 U12.10 | length 408.9
  Top Layer w6: v1(633,1425) 696,1425 710,1411 710,1383.3 697.7,1371 684.97,1371 649,1335.03 649,1266 701.84,1213.16 v1(701.84,1204.84)
  Bottom Layer w6: v1(633,1425) 662.89,1425 U3.19@663.1,1424.79 ; v1(701.84,1204.84) U12.10@701.84,1239.98
SCK_LOCAL: U13.3 U18.4 | length 62.8
  Bottom Layer w6: U18.4@630.18,830.26 638.57,821.87 U13.3@689.52,821.87
SCL': U7.25 U15.4 | length 2961.3
  Top Layer w6: v1(801,1744) 806.47,1744 1081.47,2019 1719.16,2019 2303,1435.16 2303,1098.03 2221.29,1016.31 2025.4,1016.31 2005.09,996 1956.3,996 1934,973.7 v1(1934,960)
  Bottom Layer w6: U15.4@644.62,1745.48 644.62,1761.62 649,1766 681.03,1766 724.03,1723 751.12,1723 763.12,1735 792,1735 v1(801,1744) ; v1(1934,960) 1934,973.7 1956.3,996 1974.58,996 2010,1031.42 U7.25@2010,1049.21
SCL_DK: SB28.1 U15.3 | length 148.1
  Bottom Layer w6: U15.3@628.87,1745.48 628.87,1765.87 641,1778 686,1778 714,1750 SB28.1@740,1750
SDA': U7.24 U15.8 | length 2911.6
  Top Layer w6: v1(778,1702) 778,1754.97 788.03,1765 810.5,1765 1076.5,2031 1724.13,2031 2315,1440.13 2315,1093.06 2226.26,1004.31 2030.37,1004.31 2001.06,975 v1(1965,975)
  Bottom Layer w6: U15.8@669.23,1689.38 765.38,1689.38 v1(778,1702) ; v1(1965,975) 1970.55,975 2025.75,1030.2 U7.24@2025.75,1049.21
SDA_DK: SB27.1 U15.7 | length 198.8
  Bottom Layer w6: U15.7@669.25,1705.1 750.19,1705.1 768.09,1723 812,1723 840,1751 840,1760
SPI_CTRL_3V3: R13.2 TP9.1 U7.6 U12.7 U12.8 U12.9 | length 2232.2
  Top Layer w6: v1(748,1249) 799,1300 926,1300 v1(938,1312)
  Bottom Layer w6: U12.9@721.53,1239.98 738.98,1239.98 v1(748,1249) ; R13.2@736.31,1202 748,1213.69 v1(748,1249) ; U12.7@753.02,1291.16 753.02,1254.02 v1(748,1249) ; TP9.1@960,1230 960,1290 v1(938,1312) 923,1327 923,1578.03 954.97,1610 975,1610 1006,1579 1026,1579 1045,1598 1351.67,1598 1393.67,1640 1828.06,1640 1881.31,1586.74 1881.31,1381.69 1946.25,1316.75 1946.25,1257.19 1908.48,1219.42 1908.48,1163.02 1915,1156.5 U7.6@1934.21,1156.5
U15_NC1: U15.1 | length 32.1
  Bottom Layer w15: U15.1@594.38,1751.48 594.38,1783.62
U15_NC2: U15.5
U15_NC3: U15.9
U15_NC4: U15.13
U16_NC1: U16.1 | length 40
  Bottom Layer w15: U16.1@359,1753 359,1793
U16_NC2: U16.5
U16_NC3: U16.9 | length 30
  Bottom Layer w15: 414,1645 414,1675
U16_NC4: U16.13 | length 31.9
  Bottom Layer w15: U16.13@336,1686.61 336,1666 344,1658
U17_COM1: U17.16 | length 40
  Bottom Layer w15: U17.16@107,1740 107,1780
U17_COM4: U17.12 | length 73.5
  Bottom Layer w8: 132.67,1649 132.67,1659.67 137.38,1664.38 U17.12@137.38,1680.52
  Bottom Layer w15: 132.67,1609 132.67,1649
U17_NC1: U17.1 | length 30.5
  Bottom Layer w15: U17.1@134.38,1749.48 134.38,1780
U17_NC2: U17.5
U17_NC3: U17.9 | length 73.4
  Bottom Layer w8: 180,1649 180,1658 184.62,1662.62 U17.9@184.62,1680.52
  Bottom Layer w15: 180,1609 180,1649
U17_NC4: U17.13 | length 82.6
  Bottom Layer w8: 109,1649 109,1666 112.77,1669.77 U17.13@112.77,1690
  Bottom Layer w15: 109,1609 109,1649
U17_NO1: U17.15 | length 84.3
  Bottom Layer w6: 77,1739 95.13,1720.87 U17.15@112.77,1720.87
  Bottom Layer w15: 77,1739 77,1780
U17_NO4: U17.11 | length 71.4
  Bottom Layer w8: U17.11@153,1679 153,1662 156.33,1658.67 156.33,1649
  Bottom Layer w15: 156.33,1609 156.33,1649
V5V: P1.5 | length 115.4
  Bottom Layer w30: P1.5@1500,72.32 1500,130 P1.5@1500,187.68
VBU: Bat1.1 R8.2 U4.7 | length 985
  Bottom Layer w15: Bat1.1@225,470.16 291.16,470.16 461.5,640.5 461.5,775.5 247.16,989.84 Bat1.1@225,989.84 263.69,1028.53 263.69,1107 276.48,1119.8 U4.7@342.86,1119.8
VCC_HF_XTAL: C22.2 C23.2 Q1.3 U10.14 U11.8 | length 448.1
  Bottom Layer w10: U10.14@1508.16,1288.06 1508.16,1350.53 C22.2@1507.69,1351 1511.69,1355 1550,1355 1655.41,1249.59 Q1.3@1735.6,1249.59 1735.6,1252.6 1763.69,1280.69 C23.2@1763.69,1305 1763.69,1348.95 U11.8@1763.17,1349.47
VDD_3V3: C2.2 C5.2 C7.2 C8.2 C9.2 C12.2 C26.2 C27.1 C33.1 C34.1 C35.1 Q1.4 Q2.4 Q4.4 R3.1 R5.1 R15.1 R16.1 U1.3 U1.5 U2.1 U3.20 U5.14 U7.4 U7.18 U12.14 U13.15 U18.5 U19.5 U20.5 U21.5 | length 10976.6
  Top Layer w8: v1(1800.31,1139.69) 1800,1139.37 1800,1083.13 1839,1044.13 1839,925 1855,909 1855,899
  Top Layer w10: 184,1270 186,1272 v1(293,1272) 337,1272 v1(357,1292) ; v1(450,839) 459,830 v1(502,830) 502,754 602,654 ; v1(526.31,1290.69) 535.31,1299.69 v1(535.31,1451.69) ; v1(1204,1145) 1233,1145 1245,1157 ; v1(1244,1075) 1244,1155 ; 1855,899 1860.53,899 1890,928.47 1890,966.47 1945.53,1022 1994.32,1022 2021.63,1049.31 v1(2150.31,1049.31)
  Top Layer w15: v1(602,569) 602,381 638,345 1073,345 1107,311 1107,287 1166.5,227.5 2255.5,227.5 v1(2540,512)
  Top Layer w25: 184,1270 110,1196 v1(110,1159) 110,844.5 385.5,569 v1(602,569) ; 186,1272 365.69,1451.69 v1(535.31,1451.69) ; 1248,1155 1373,1280 1381,1280 ; 1855,899 1815.5,859.5 1556.5,859.5 1449,752 1449,710 1308,569 v1(602,569) ; v1(1914,1312) 1909,1307 1559,1307 1532,1280 1381,1280 ; v1(602,569) 602,654 v1(684,736) 699,736 891,928 891,1124 1082,1315 1346,1315 1381,1280
  Bottom Layer w8: v1(1800.31,1139.69) C8.2@1860,1139.69 1883.31,1139.69 1898,1125 U7.4@1934.21,1125 ; U7.18@2085.79,1125 2135.31,1125 C9.2@2150.31,1110 v1(2150.31,1049.31)
  Bottom Layer w10: v1(293,1272) 311,1254 R16.1@311,1225.68 ; v1(357,1292) 364,1299 C35.1@388.31,1299 388.31,1278.06 U21.5@368.26,1258 ; U20.5@435,943.26 412.06,943.26 C34.1@392,963.31 392,922 450,864 v1(450,839) ; v1(502,830) 502.26,830.26 U18.5@579,830.26 ; v1(526.31,1290.69) C26.2@586,1290.69 586.47,1291.16 U12.14@630.98,1291.16 ; v1(535.31,1451.69) 551,1451.69 563,1439.69 593.53,1439.69 618,1464.16 U3.20@643.42,1464.16 ; v1(684,736) 699,736 714.13,751.13 U13.15@714.13,765.77 ; U19.5@864.26,1089 864.26,1097.94 C27.1@898.31,1132 v1(929.31,1163) ; U1.3@1033.13,1046.73 1033.13,1073.57 1070.53,1110.98 ; U1.5@1070.53,1141.22 1070.53,1110.98 ; U5.14@1128.69,975 1128.69,990.82 C7.2@1179.84,1041.98 1179.84,1050.84 1204,1075 v1(1244,1075) ; v1(1204,1145) 1204,1135 1171.29,1102.29 C12.2@1164.53,1102.29 1079.21,1102.29 1070.53,1110.98
  Bottom Layer w15: Q1.4@1810.4,1249.59 1857.09,1249.59 R3.1@1863,1243.68 ; v1(2540,512) 2696,512 2723,539 2723,626 2695.32,653.68 R5.1@2667,653.68 2659.09,661.59 Q2.4@2616.4,661.59
  Bottom Layer w20: C2.2@602,455.53 630.47,455.53 648.4,437.6 U2.1@673.91,437.6
  Bottom Layer w25: v1(110,1159) 81.91,1187.09 81.91,1224.41 Q4.4@125.6,1224.41 ; R3.1@1863,1243.68 1914,1294.69 v1(1914,1312)
  Bottom Layer w30: C2.2@602,456.15 v1(602,569)
VDD_LF_XTAL: C13.2 C14.2 C15.2 Q2.3 U6.16 U8.6 U9.5 | length 1186.9
  Top Layer w15: v1(1936,822) 1936,793 2008,721 2234,721 v1@2250.5,737.5 ; v1(2170.95,946.05) 2170.95,863.99 2250.5,784.43 v1@2250.5,737.5 ; v1(2251,737) v1@2250.5,737.5
  Bottom Layer w15: v1(1936,822) 1935.69,822.31 C15.2@1935.69,855 1936.15,855.47 U8.6@1985.2,855.47 ; U6.16@2160.76,863.61 2160.76,906.55 C14.2@2160.26,907.05 2160.26,935.36 v1(2170.95,946.05) ; v1(2251,737) 2251,706.94 2269.44,688.5 2269.5,688.5 2281,677 2281,657.06 ; U9.5@2281,629.46 2281,657.06 ; C13.2@2447,655.69 2435.31,644 2340.59,644 2323,661.59 2285.53,661.59 2281,657.06 ; C13.2@2447,661.59 Q2.3@2541.6,661.59
VDISP: C16.2 C18.2 C19.2 P6.6 P6.7 Q3.3 | length 505.3
  Bottom Layer w10: P6.7@1378.35,688.09 1378.35,728.41 C19.2@1378.35,729.05 ; P6.6@1398.03,688.09 1398.03,703.7 1415.87,721.54 C18.2@1415.87,728.41
  Bottom Layer w15: C16.2@1127.87,649.41 1208.41,649.41 1287.41,728.41 1378.35,728.41 C18.2@1415.87,728.41
  Bottom Layer w20: Q3.3@1033.52,645.63 1102.33,645.63 1106.11,649.41 C16.2@1127.87,649.41
VDISP_SRC: Q3.4 R6.1 U13.16 | length 451.3
  Bottom Layer w15: U13.16@695,765.77 664.77,765.77 649,750 649,694 707.56,635.44 R6.1@907.87,635.44
  Bottom Layer w20: R6.1@907.87,635.44 909.19,634.13 925.87,634.13 937.87,646.13 Q3.4@962.01,646.13
VIN: P1.8 | length 115.4
  Bottom Layer w15: P1.8@1800,72.32 1800,130 P1.8@1800,187.68
VIO: C28.2 C29.2 C30.2 C31.2 C32.2 P1.1 P1.2 P1.4 Q5.4 R17.1 SW2.1 U13.1 U13.14 U14.14 U15.14 U16.14 U17.14 | length 6428.8
  Top Layer w8: v1(265,1707) 291,1681 291,1604 v1(314,1581) ; v1(320,1866) v1(320,1985) ; v1(431,1575) 469,1613 469,1675 v1(501,1707)
  Top Layer w9: v1(655,646.69) v1(700.31,692) ; v1(1664,533) 1787,533 1802,548 1802,570.82 1757,615.82 1757,714 v1(1776,733)
  Top Layer w15: v1(314,1581) 314,1497 53,1236 53,822 745,130 v1(1100,130)
  Top Layer w30: v1(1100,130) v1(1200,130) v1(1400,130)
  Bottom Layer w8: U17.14@112.77,1705.13 71.44,1705.13 C32.2@71,1704.69 47,1680.69 47,1597 63,1581 v1(314,1581) 320,1575 v1(431,1575) ; v1(320,1866) 265,1811 v1(265,1707) 267.31,1704.69 C31.2@295,1704.69 295.44,1705.13 U16.14@336.77,1705.13 ; v1(320,1985) 320,2042.38 SW2.1@322.9,2045.28 ; v1(501,1707) 503.31,1704.69 C30.2@531,1704.69 531.44,1705.13 U15.14@572.77,1705.13
  Bottom Layer w9: 494.5,648 495.81,646.69 v1(655,646.69) ; v1(700.31,692) C29.2@730.31,722 729.87,722.44 U13.14@729.87,765.77 ; P1.1@1100,187.68 1107,194.68 1107,390 1250,533 v1(1664,533) ; U14.14@1727.23,686.87 1767.19,686.87 C28.2@1776,695.69 v1(1776,733)
  Bottom Layer w10: 668,790.38 U13.1@689.52,790.38
  Bottom Layer w15: v1(499,372) 494.5,376.5 494.5,648 494.5,724.5 560.38,790.38 668,790.38
  Bottom Layer w30: 1044,281 1044,243.68 P1.1@1100,187.68 v1(1100,130) ; P1.2@1200,72.32 P1.2@1200,187.68 ; P1.4@1400,72.32 P1.4@1400,187.68
VRAM: C6.2 Q4.3 U4.8 | length 185.2
  Bottom Layer w10: Q4.3@200.4,1224.41 200.4,1206.76 C6.2@261,1146.16 ; C6.2@261,1145.39 U4.8@342.86,1145.39
VREG_SRC: C1.2 C4.2 C10.2 Q5.3 R1.2 SW1.1 SW1.4 U2.3 U2.5 U3.1 U7.12 | length 6959.7
  Top Layer w6: v1@1960,946 v1@1960.5,946.5 ; v1(1962,945) 1988.03,945 2035.34,992.31 2547,992.31
  Top Layer w15: v1(463,1498) 353,1498 78,1223 78,831 585,324 1055,324 v1(1076,303)
  Top Layer w20: v1(1076,303) 1076,278 1150,204 2282,204 2630,552 2630,640 2555,715 2555,1225.63 v1(2510.31,1270.31)
  Bottom Layer w6: U2.3@673.91,512.4 711.6,512.4 749,475 U2.5@768.4,475 ; v1(1962,945) 1978.31,945 R1.2@1995.31,962
  Bottom Layer w8: C10.2@2025,1270.31 2025.75,1269.57 U7.12@2025.75,1200.79
  Bottom Layer w10: v1(463,1498) 463,1501 469,1507 513,1507 541.69,1478.31 581,1478.31 586.53,1483.84 U3.1@643.42,1483.84 ; SW1.4@2387.9,1590.83 SW1.1@2387.9,1445.17 2387.9,1392.73 v1(2510.31,1270.31)
  Bottom Layer w15: C10.2@2025,1270.31 v1(2510.31,1270.31)
  Bottom Layer w20: U2.5@768.4,475 839.85,475 C1.2@840,475.15 998.85,475.15 1036.59,437.41 Q5.3@1036.59,356.4 1060,356.4 1076,340.4 v1(1076,303)
pads on no net: Bat1.0 Fid1.0 Fid2.0 P5.1 P5.2 P5.3 P5.4 P5.5 P6. U3.21 U4.3 U5.5 U7.11 U12.5 U13.10 U18.1 U19.1 U20.1 U21.1

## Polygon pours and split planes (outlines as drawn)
GND on Bottom Layer "Bottom_Layer-GND" (solid, remove dead copper, pour order 6): -410.29,-273.14 -410.29,2517.49 -400.99,2533.72 2950,2533.72 2950,-273.14
GND on Top Layer "Top_Layer-GND" (solid, remove dead copper, pour order 8): -140.68,-263.3 -140.68,2457.41 -132.15,2473.23 2931,2473.23 2931,-263.3

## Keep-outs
Top Layer:
  circle w6: c2600,330 r94.49
Keep-Out Layer:
  circle w6: c550,130 r90
  circle w6: c600,2030 r90
  circle w6: c2600,1430 r94.49
  lines w6: 2512.34,294.73 ccw(c2600,330) 2516.3,373.84
  lines w10: 0,40 ccw(c40,40) 40,0 2760,0 ccw(c2760,40) 2800,40 2800,2120 ccw(c2760,2120) 2760,2160 40,2160 ccw(c40,2120) 0,2120 0,40

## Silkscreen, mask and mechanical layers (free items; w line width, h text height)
Top Overlay:
  lines w6: 852.76,437.48 1225.39,437.48 1598.23,437.48
  lines w7: 852.76,437.48 852.76,1710.71 1962.99,1710.71 1962.99,437.48 ; 1213.58,404.09 1213.58,437.48 ; 1586.42,404.09 1586.42,437.48 ; 163.78,437.48 163.78,2123.31 2636.22,2123.31 2636.22,437.48 163.78,437.48
  text "NORDIC" at 1897.67,269.92 h150
  text "400139" at 34.34,219.81 h80
  text "SEMICONDUCTOR" at 1894.28,211.23 h65
  text "0233RUBR" at 34.34,159.81 h65
  text "www.nordicsemi.com" at 1702,147 h83
Bottom Overlay:
  text "MODE" at 335,2092 h80
  text "D1" at 2378,1868.64 h70 r270
  text "D2" at 2278,1862.99 h70 r270
  text "D0" at 2478,1862.99 h70 r270
  text "D9" at 1518,1862.81 h70 r270
  text "D8" at 1618,1862.69 h70 r270
  text "D7" at 1778,1862.69 h70 r270
  text "D6" at 1878,1862.23 h70 r270
  text "D5" at 1978,1862 h70 r270
  text "D3" at 2178,1862.58 h70 r270
  text "D4" at 2078,1861.65 h70 r270
  text "D11" at 1318,1840.72 h70 r270
  text "D12" at 1218,1835.06 h70 r270
  text "D10" at 1418,1835.06 h70 r270
  text "D13" at 1118,1834.65 h70 r270
  text "M1" at 282,1826.72 h100 r270
  text "SCL" at 718,1824.1 h70 r270
  text "M0" at 164,1820.72 h100 r270
  text "SDA" at 818,1817.16 h70 r270
  text "GND" at 1018,1814.48 h70 r270
  text "AREF" at 918,1786.79 h70 r270
  text "ADDR1" at 2190,1536 h80
  text "ADDR0" at 2190,1453 h80
  text "MODE: / M1: DEFAULT / M0: LCD only" at 1355,1380 h80
  text "1" at 2347,1368 h100 r270
  text "0" at 2229,1362 h100 r270
  text "VDD" at 1074.75,425.72 h70 r270
  text "VDD" at 1174.75,425.72 h70 r270
  text "RST" at 1274.75,425.72 h70 r270
  text "VDD" at 1374.75,425.72 h70 r270
  text "5V" at 1474.75,425.72 h70 r270
  text "GND" at 1574.75,425.72 h70 r270
  text "GND" at 1674.75,425.72 h70 r270
  text "I2C address:" at 513,364 h70
  text "ADDR[1:0] | Address" at 513,314 h70
  text "00         |     0x3E" at 427,264 h70
  text "A4" at 2378.75,241.01 h70 r270
  text "A3" at 2278.75,240.08 h70 r270
  text "A5" at 2478.75,240.66 h70 r270
  text "A0" at 1978.75,239.67 h70 r270
  text "A2" at 2178.75,239.67 h70 r270
  text "A1" at 2078.75,234.02 h70 r270
  text "01         |     0x3F" at 428,214 h70
  text "10         |     0x70" at 426,164 h70
  text "11         |     0x71" at 426,114 h70
Mechanical 1:
  lines w10: 0,40 ccw(c40,40) 40,0 2760,0 ccw(c2760,40) 2800,40 2800,2120 ccw(c2760,2120) 2760,2160 40,2160 ccw(c40,2120) 0,2120 0,40
Mechanical 3:
  lines w10: 0,2290 0,-130 ccw(c40,-130) 40,-170 2760,-170 ; 0,2290.51 cw(c40,2290) 40.51,2330 ; 40,2330 2760,2330 cw(c2760,2290) 2800,2290 2800,-130 ; 2760.51,-170 ccw(c2760,-130) 2800,-129.49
